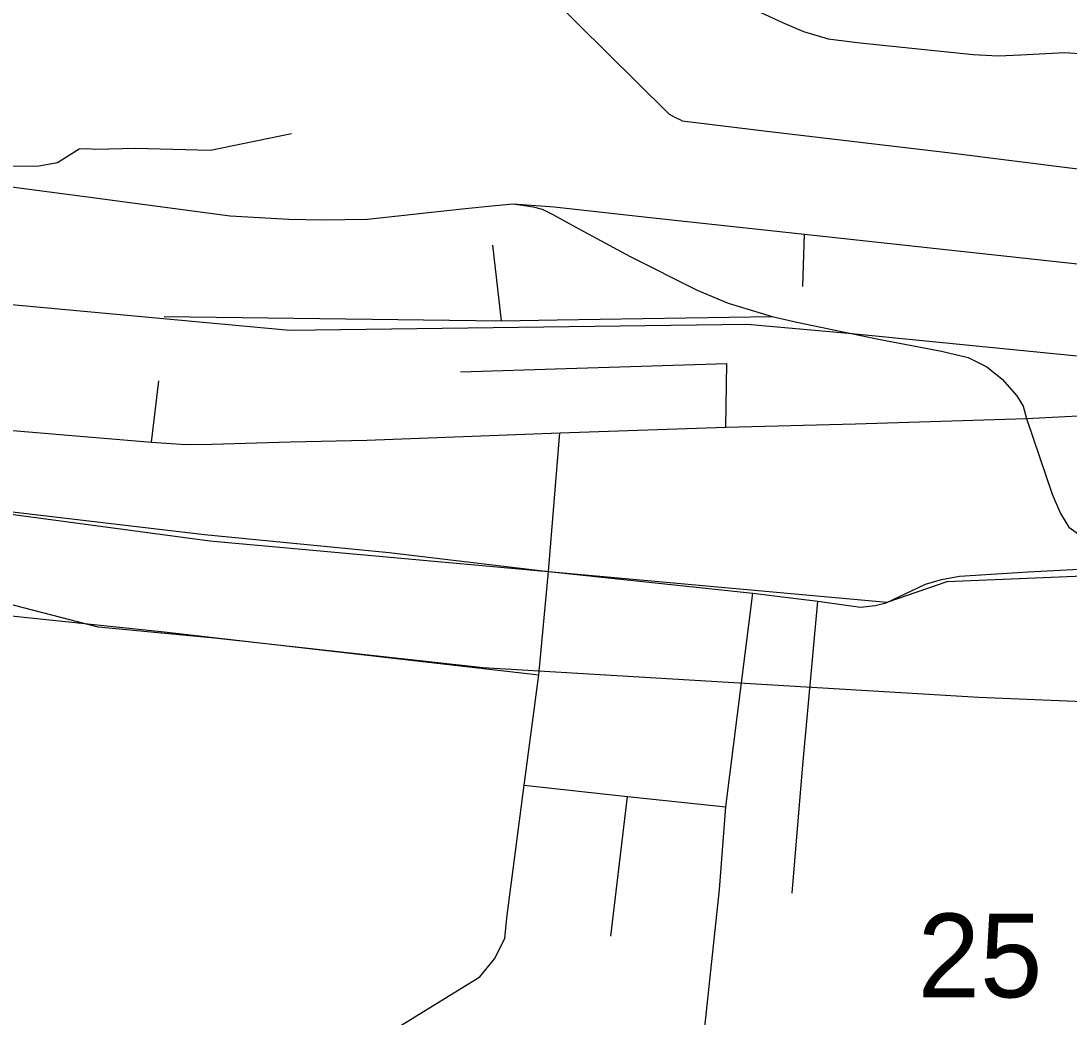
# Model space of a CAD drawing. Extents: x -8.2 to 38.5, y -0.1 to 21.9.
# Drawn here: x 4.638 to 5.161, y 15.594 to 16.091 of the extents above; entities that cross this region are included whole.
import ezdxf

# ---------------------------------------------------------------- set-up
doc = ezdxf.new("R2010")
doc.units = 0
for name, color, linetype in [('GM_X_County_Road_Text', 7, 'Continuous'), ('GM_X_Township_Subdivision_Text', 7, 'Continuous'), ('GM_X_Township_Text', 7, 'Continuous'), ('GM_X_US_Location', 7, 'Continuous')]:
    doc.layers.add(name, color=color, linetype=linetype)

msp = doc.modelspace()

# ---------------------------------------------------------------- linework, layer by layer
at = {"layer": 'GM_X_Township_Subdivision_Text'}
for p, q in [((5.02859, 15.95854), (5.02942, 15.98463)), ((4.87797, 15.94135), (4.87368, 15.97906)), ((4.99012, 15.88826), (4.99063, 15.91994)), ((4.7033, 15.88067), (4.70686, 15.91138)), ((4.93268, 15.63411), (4.94096, 15.70393))]:
    msp.add_line(p, q, dxfattribs=at)
for points in [[(4.96834, 16.04118), (4.96504, 16.04261), (4.96198, 16.0444), (4.96086, 16.04543), (4.90097, 16.10473), (4.88113, 16.16337)], [(4.99245, 16.10244), (5.01831, 16.09032), (5.02882, 16.08584), (5.04124, 16.08207), (5.05714, 16.08011), (5.11356, 16.07434), (5.12607, 16.07361), (5.13747, 16.07405), (5.15915, 16.07534), (5.169, 16.07469), (5.18833, 16.07338), (5.20337, 16.07199)], [(4.96834, 16.04118), (5.00922, 16.03624), (5.03609, 16.03307), (5.10232, 16.02526), (5.19371, 16.01366), (5.20406, 16.01226), (5.21295, 16.01065)], [(4.61663, 16.01044), (4.61992, 16.01699), (4.63308, 16.01847), (4.64705, 16.01863), (4.65625, 16.02044), (4.66708, 16.02719), (4.67128, 16.02743), (4.67544, 16.02709), (4.69518, 16.0275), (4.73267, 16.02652), (4.77317, 16.03491)], [(4.88396, 15.99973), (4.90434, 15.99825), (4.95087, 15.99299), (5.02942, 15.98463), (5.18867, 15.9672), (5.22141, 15.96468), (5.23317, 15.963), (5.33673, 15.94201)], [(4.70953, 15.94341), (4.87797, 15.94135), (4.90581, 15.94175), (5.01318, 15.94352)], [(4.85753, 15.91587), (4.91032, 15.91754), (4.99063, 15.91994)], [(4.59094, 15.81148), (4.59335, 15.79827), (4.70956, 15.7861), (4.89676, 15.76453)], [(4.97073, 15.47238), (4.96888, 15.47597), (4.9688, 15.4814), (4.96916, 15.48738), (4.971, 15.50755), (4.98691, 15.65736), (4.99015, 15.69862), (5.00354, 15.80537)], [(5.02323, 15.65557), (5.02829, 15.71774), (5.03602, 15.80133)], [(4.88944, 15.70943), (4.94096, 15.70393), (4.99015, 15.69862)]]:
    msp.add_lwpolyline(points, dxfattribs=at)
at = {"layer": 'GM_X_Township_Text'}
for points in [[(4.61663, 16.01044), (4.67507, 16.00267), (4.71872, 15.99687), (4.74259, 15.99377), (4.77184, 15.992), (4.78862, 15.99179), (4.81112, 15.992), (4.85847, 15.99727), (4.87491, 15.99891), (4.88396, 15.99973), (4.89383, 15.99817), (4.89839, 15.99703), (4.90399, 15.99427), (4.91513, 15.98814), (4.94232, 15.97342), (4.97569, 15.95665), (4.99131, 15.95008), (5.01318, 15.94352), (5.02555, 15.94072), (5.0654, 15.93229), (5.09784, 15.92624), (5.11102, 15.92293), (5.12034, 15.91837), (5.12809, 15.91218), (5.13545, 15.90383), (5.1385, 15.89867), (5.14022, 15.89257)], [(4.32451, 15.9768), (4.36328, 15.9644), (4.40904, 15.94751), (4.45898, 15.92945), (4.47271, 15.92412), (4.53892, 15.90529), (4.60016, 15.88949), (4.6321, 15.88668), (4.67749, 15.8829), (4.7033, 15.88067), (4.72043, 15.87956), (4.73356, 15.87978), (4.7727, 15.88088), (4.81082, 15.8817), (4.90713, 15.88539), (4.99012, 15.88826), (5.05489, 15.88992), (5.14022, 15.89257)], [(5.14022, 15.89257), (5.18541, 15.89482), (5.31655, 15.89649)], [(5.14022, 15.89257), (5.15298, 15.85486), (5.15715, 15.84508), (5.16132, 15.83831), (5.16646, 15.83473), (5.17936, 15.82951), (5.20756, 15.81819)], [(4.44755, 15.88801), (4.46835, 15.8839), (4.5292, 15.8681), (4.5955, 15.8513), (4.6311, 15.8463), (4.72978, 15.83462), (4.82189, 15.82572), (4.9015, 15.81619), (5.00354, 15.80537), (5.03602, 15.80133), (5.0574, 15.79844), (5.06468, 15.79913), (5.07012, 15.80052), (5.08986, 15.80977), (5.0977, 15.81213), (5.10681, 15.81378), (5.1411, 15.81602), (5.18572, 15.81826), (5.20756, 15.81819)], [(4.76368, 15.55009), (4.86716, 15.6139), (4.87453, 15.62284), (4.87971, 15.63303), (4.88066, 15.6433), (4.88944, 15.70943), (4.89676, 15.76453), (4.9015, 15.81619), (4.90713, 15.88539)]]:
    msp.add_lwpolyline(points, dxfattribs=at)
at = {"layer": 'GM_X_US_Location'}
for points in [[(5.42231, 15.84691), (5.40957, 15.89323), (5.38868, 15.90966), (5.35734, 15.91863), (5.18572, 15.92162), (5.05141, 15.93506), (5.00067, 15.93954), (4.77234, 15.93654), (4.62609, 15.94997), (4.45448, 15.99924), (4.34704, 16.03956), (4.16199, 16.09481), (4.08887, 16.1172), (4.02918, 16.12019), (3.84612, 16.11588), (3.54158, 16.17911), (3.37065, 16.20444), (3.15964, 16.25091), (3.04991, 16.30793), (2.98497, 16.37271), (2.97481, 16.51211), (2.969, 16.6094), (2.95384, 16.66998)], [(5.40181, 15.59132), (5.39352, 15.60269), (5.32387, 15.67083), (5.26054, 15.72787), (5.22571, 15.7453), (5.19246, 15.75006), (5.11647, 15.75323), (4.86892, 15.76816), (4.73477, 15.78286), (4.67658, 15.78838), (4.42055, 15.85455), (4.33051, 15.88396), (4.23373, 15.91214), (4.14757, 15.93855), (4.06367, 15.97023)], [(5.40181, 15.59132), (5.40878, 15.60521), (5.41312, 15.61475), (5.41485, 15.62515), (5.41485, 15.63512), (5.41225, 15.64336), (5.33774, 15.74089), (5.31565, 15.7604), (5.27926, 15.77817), (5.2046, 15.81536), (5.10046, 15.81107), (5.07056, 15.80076), (4.73233, 15.83128), (4.59941, 15.84905), (4.44837, 15.88946)]]:
    msp.add_lwpolyline(points, dxfattribs=at)

# ---------------------------------------------------------------- texts
at = {"layer": 'GM_X_County_Road_Text'}
msp.add_text('25', height=0.041856, rotation=0, dxfattribs=at).set_placement((5.08588, 15.60357))

doc.saveas('drawing.dxf')
